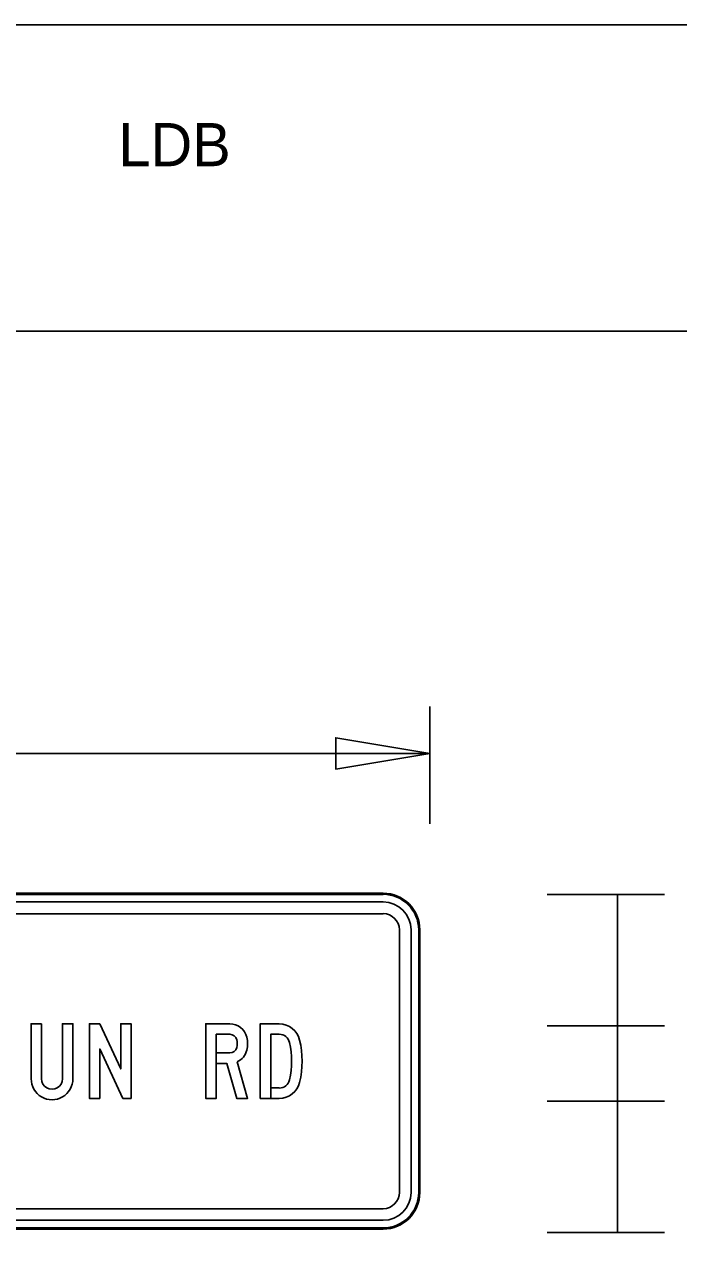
# Model space of a CAD drawing. Extents: x 766449 to 768137, y 650958 to 652521.
# Drawn here: x 767137.3 to 767210.9, y 652114.7 to 652254.2 of the extents above; entities that cross this region are included whole.
import ezdxf

# ---------------------------------------------------------------- set-up
doc = ezdxf.new("R2010")
doc.units = 0
doc.layers.add('Default', color=7, linetype='Continuous')
doc.layers.add('Text', color=7, linetype='Continuous')

msp = doc.modelspace()

# ---------------------------------------------------------------- linework, layer by layer
at = {"layer": 'Default'}
for p, q in [((767182.93, 652164.2), (767182.93, 652177.43)), ((767068.61, 652172.14), (767182.93, 652172.14)), ((767182.93, 652164.2), (767182.93, 652164.2)), ((767177.68, 652156.39), (767072.43, 652156.39)), ((767177.68, 652156.39), (767072.43, 652156.39)), ((767177.68, 652156.39), (767072.43, 652156.39)), ((767177.68, 652156.39), (767072.43, 652156.39)), ((767072.43, 652156.26), (767177.68, 652156.26)), ((767196.17, 652156.26), (767209.4, 652156.26)), ((767196.17, 652156.26), (767196.17, 652156.26)), ((767204.11, 652141.44), (767204.11, 652156.26)), ((767177.68, 652155.41), (767072.43, 652155.41)), ((767177.68, 652155.41), (767072.43, 652155.41)), ((767177.68, 652155.41), (767072.43, 652155.41)), ((767177.68, 652154.09), (767072.43, 652154.09)), ((767072.43, 652154.09), (767177.68, 652154.09)), ((767072.43, 652154.09), (767177.68, 652154.09)), ((767179.52, 652122.69), (767179.52, 652152.26)), ((767179.52, 652152.26), (767179.52, 652122.69)), ((767179.52, 652152.26), (767179.52, 652122.69)), ((767180.84, 652122.69), (767180.84, 652152.26)), ((767180.84, 652122.69), (767180.84, 652152.26)), ((767180.84, 652122.69), (767180.84, 652152.26)), ((767181.69, 652152.26), (767181.69, 652122.69)), ((767181.82, 652122.69), (767181.82, 652152.26)), ((767181.82, 652122.69), (767181.82, 652152.26)), ((767181.82, 652122.69), (767181.82, 652152.26)), ((767181.82, 652122.69), (767181.82, 652152.26)), ((767139.2, 652141.68), (767139.2, 652135.48)), ((767139.2, 652141.68), (767139.2, 652135.48)), ((767139.2, 652141.68), (767139.2, 652135.48)), ((767160.41, 652141.68), (767157.7, 652141.68)), ((767160.41, 652140.5), (767160.41, 652140.5)), ((767196.17, 652141.44), (767209.4, 652141.44)), ((767196.17, 652141.44), (767209.4, 652141.44)), ((767204.11, 652141.44), (767204.11, 652132.98)), ((767160.41, 652138.4), (767160.41, 652138.4)), ((767160.41, 652138.4), (767160.41, 652138.4)), ((767165.02, 652134.45), (767165.99, 652134.45)), ((767165.99, 652134.45), (767165.02, 652134.45)), ((767165.99, 652134.45), (767165.02, 652134.45)), ((767165.99, 652133.27), (767165.99, 652133.27)), ((767196.17, 652132.98), (767209.4, 652132.98)), ((767196.17, 652132.98), (767209.4, 652132.98)), ((767204.11, 652118.16), (767204.11, 652132.98)), ((767072.43, 652120.85), (767177.68, 652120.85)), ((767177.68, 652120.85), (767072.44, 652120.85)), ((767177.68, 652120.85), (767072.44, 652120.85)), ((767072.43, 652119.54), (767177.68, 652119.54)), ((767072.44, 652119.54), (767177.68, 652119.54)), ((767072.44, 652119.54), (767177.68, 652119.54)), ((767177.68, 652118.68), (767072.43, 652118.68)), ((767072.43, 652118.55), (767177.68, 652118.55)), ((767072.43, 652118.55), (767177.68, 652118.55)), ((767072.43, 652118.55), (767177.68, 652118.55)), ((767072.43, 652118.55), (767177.68, 652118.55)), ((767196.17, 652118.16), (767209.4, 652118.16)), ((767196.17, 652118.16), (767196.17, 652118.16))]:
    msp.add_line(p, q, dxfattribs=at)
for points in [[(767182.93, 652172.14), (767172.35, 652170.38), (767172.35, 652173.91)], [(767148.37, 652133.27), (767149.29, 652133.27), (767149.29, 652141.68), (767148.12, 652141.68), (767148.12, 652136.6), (767145.75, 652141.68), (767144.59, 652141.68), (767144.59, 652133.27), (767145.76, 652133.27), (767145.76, 652138.86)], [(767148.37, 652133.27), (767149.29, 652133.27), (767149.29, 652141.68), (767148.12, 652141.68), (767148.12, 652136.6), (767145.75, 652141.68), (767144.59, 652141.68), (767144.59, 652133.27), (767145.76, 652133.27), (767145.76, 652138.86)], [(767148.37, 652133.27), (767149.29, 652133.27), (767149.29, 652141.68), (767148.12, 652141.68), (767148.12, 652136.6), (767145.75, 652141.68), (767144.59, 652141.68), (767144.59, 652133.27), (767145.76, 652133.27), (767145.76, 652138.86)]]:
    msp.add_lwpolyline(points, close=True, dxfattribs=at)
for points in [[(767138.03, 652135.48), (767138.03, 652141.68), (767139.2, 652141.68)], [(767138.03, 652135.48), (767138.03, 652141.68), (767139.2, 652141.68)], [(767138.03, 652135.48), (767138.03, 652141.68), (767139.2, 652141.68)], [(767141.56, 652135.48), (767141.56, 652141.68), (767142.73, 652141.68), (767142.73, 652135.48)], [(767141.56, 652135.48), (767141.56, 652141.68), (767142.73, 652141.68), (767142.73, 652135.48)], [(767141.56, 652135.48), (767141.56, 652141.68), (767142.73, 652141.68), (767142.73, 652135.48)], [(767157.7, 652141.68), (767157.7, 652133.27), (767158.88, 652133.27), (767158.88, 652137.22), (767160.06, 652137.22), (767161.19, 652133.27), (767162.41, 652133.27), (767161.24, 652137.4)], [(767160.41, 652140.5), (767158.88, 652140.5), (767158.88, 652133.27), (767157.7, 652133.27), (767157.7, 652141.68), (767160.41, 652141.68)], [(767160.41, 652140.5), (767158.88, 652140.5), (767158.88, 652133.27), (767157.7, 652133.27), (767157.7, 652141.68), (767160.41, 652141.68)], [(767165.99, 652141.68), (767163.84, 652141.68), (767163.84, 652133.27), (767165.99, 652133.27)], [(767165.99, 652141.68), (767163.84, 652141.68), (767163.84, 652133.27), (767165.02, 652133.27), (767165.02, 652140.5), (767165.99, 652140.5)], [(767165.99, 652141.68), (767163.84, 652141.68), (767163.84, 652133.27), (767165.02, 652133.27), (767165.02, 652140.5), (767165.99, 652140.5)], [(767160.41, 652140.5), (767158.88, 652140.5), (767158.88, 652138.4), (767160.41, 652138.4)], [(767165.99, 652140.5), (767165.02, 652140.5), (767165.02, 652134.45)], [(767161.24, 652137.4), (767162.41, 652133.27), (767161.19, 652133.27), (767160.06, 652137.22), (767158.88, 652137.22), (767158.88, 652138.4), (767160.41, 652138.4)], [(767161.24, 652137.4), (767162.41, 652133.27), (767161.19, 652133.27), (767160.06, 652137.22), (767158.88, 652137.22), (767158.88, 652138.4), (767160.41, 652138.4)], [(767165.02, 652134.45), (767165.02, 652133.27), (767165.99, 652133.27)], [(767165.02, 652134.45), (767165.02, 652133.27), (767165.99, 652133.27)]]:
    msp.add_lwpolyline(points, dxfattribs=at)
for centre, radius, start, end in [((767177.68, 652152.26), 4.14, 0, 90), ((767177.68, 652152.26), 4.14, 0, 90), ((767177.68, 652152.26), 4.14, 0, 90), ((767177.68, 652152.26), 4.14, 0, 90), ((767177.68, 652152.26), 4.01, 0, 90), ((767177.68, 652152.26), 3.15, 0, 90), ((767177.68, 652152.26), 3.15, 0, 90), ((767177.68, 652152.26), 3.15, 0, 90), ((767177.68, 652152.26), 1.84, 0, 90), ((767177.68, 652152.26), 1.84, 0, 90), ((767177.68, 652152.26), 1.84, 0, 90), ((767165.99, 652139.32), 2.35, 13.109, 90), ((767165.99, 652139.32), 2.35, 13.109, 90), ((767165.99, 652139.32), 2.35, 13.109, 90), ((767165.99, 652139.32), 1.18, 13.109, 90), ((767165.99, 652139.32), 1.18, 13.109, 90), ((767165.99, 652139.32), 1.18, 13.109, 90), ((767158.04, 652137.47), 9.33, 346.891, 13.109), ((767158.04, 652137.47), 9.33, 346.891, 13.109), ((767158.04, 652137.47), 9.33, 346.891, 13.109), ((767158.04, 652137.47), 10.51, 346.891, 13.109), ((767158.04, 652137.47), 10.51, 346.891, 13.109), ((767158.04, 652137.47), 10.51, 346.891, 13.109), ((767165.99, 652135.62), 1.18, 270, 346.891), ((767165.99, 652135.62), 1.18, 270, 346.891), ((767165.99, 652135.62), 1.18, 270, 346.891), ((767165.99, 652135.62), 2.35, 270, 346.891), ((767165.99, 652135.62), 2.35, 270, 346.891), ((767165.99, 652135.62), 2.35, 270, 346.891), ((767177.68, 652122.69), 4.14, 270, 0), ((767177.68, 652122.69), 3.15, 270, 0), ((767177.68, 652122.69), 1.84, 270, 0), ((767177.68, 652122.69), 3.15, 270, 0), ((767177.68, 652122.69), 1.84, 270, 0), ((767177.68, 652122.69), 3.15, 270, 0), ((767177.68, 652122.69), 1.84, 270, 0), ((767177.68, 652122.69), 4.14, 270, 0), ((767177.68, 652122.69), 4.14, 270, 0), ((767177.68, 652122.69), 4.14, 270, 0), ((767177.68, 652122.69), 4.01, 270, 0)]:
    msp.add_arc(centre, radius, start, end, dxfattribs=at)
for centre, major_axis, ratio, start_param, end_param in [((767160.41, 652139.7), (0, 1.98), 0.999998, 4.954755, 6.283185), ((767160.41, 652139.7), (0, 1.98), 0.999998, 4.954755, 6.283185), ((767160.41, 652139.7), (0, 1.98), 0.999998, 4.954755, 6.283185), ((767160.41, 652139.7), (0, 0.799), 0.999998, 4.954755, 6.283185), ((767160.41, 652139.7), (0, 0.799), 0.999998, 4.954755, 6.283185), ((767160.41, 652139.7), (0, 0.799), 0.999998, 4.954755, 6.283185), ((767159.39, 652139.45), (0, 3.03), 0.999998, 4.470023, 4.954755), ((767159.39, 652139.45), (0, 3.03), 0.999998, 4.470023, 4.954755), ((767159.39, 652139.45), (0, 3.03), 0.999998, 4.470023, 4.954755), ((767160.41, 652139.2), (0, 0.799), 0.999998, 3.141593, 4.470023), ((767160.41, 652139.2), (0, 0.799), 0.999998, 3.141593, 4.470023), ((767160.41, 652139.2), (0, 0.799), 0.999998, 3.141593, 4.470023), ((767159.39, 652139.45), (0, 1.85), 0.999998, 4.470023, 4.954755), ((767159.39, 652139.45), (0, 1.85), 0.999998, 4.470023, 4.954755), ((767159.39, 652139.45), (0, 1.85), 0.999998, 4.470023, 4.954755), ((767160.41, 652139.2), (0, 1.98), 0.999998, 3.574819, 4.470023), ((767160.41, 652139.2), (0, 1.98), 0.999998, 3.574819, 4.470023), ((767160.41, 652139.2), (0, 1.98), 0.999998, 3.574819, 4.470023), ((767140.38, 652135.48), (0, 2.35), 0.999993, 1.570796, 4.712389), ((767140.38, 652135.48), (0, 2.35), 0.999993, 1.570796, 4.712389), ((767140.38, 652135.48), (0, 2.35), 0.999993, 1.570796, 4.712389), ((767140.38, 652135.48), (0, 1.18), 0.999993, 1.570796, 4.712389), ((767140.38, 652135.48), (0, 1.18), 0.999993, 1.570796, 4.712389), ((767140.38, 652135.48), (0, 1.18), 0.999993, 1.570796, 4.712389)]:
    msp.add_ellipse(centre, major_axis=major_axis, ratio=ratio, start_param=start_param, end_param=end_param, dxfattribs=at)
at = {"layer": 'Text'}
msp.add_line((766921.88, 652219.7), (767346.04, 652219.7), dxfattribs=at)
msp.add_lwpolyline([(766646.04, 652254.24), (767346.04, 652254.24), (767346.04, 651768.77), (766646.04, 651768.77)], close=True, dxfattribs=at)

# ---------------------------------------------------------------- texts
msp.add_text('LDB', height=4.865, rotation=360, dxfattribs=at).set_placement((767147.86, 652238.3))

doc.saveas('drawing.dxf')
